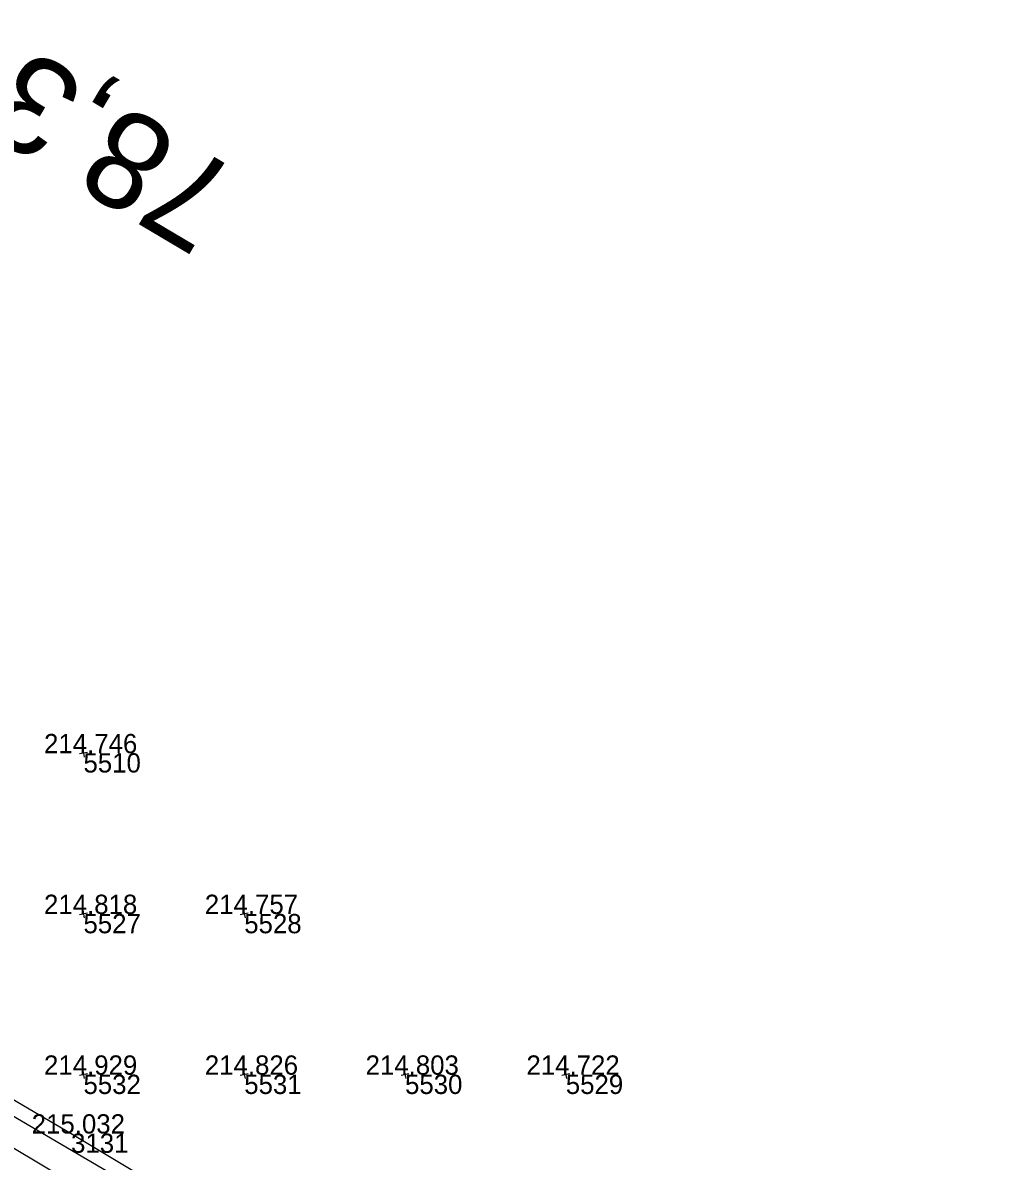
# Model space of a CAD drawing. Extents: x -556590 to -554855, y -1137918 to -1135717.
# Drawn here: x -556203.8 to -556143.5, y -1135955.4 to -1135884.6 of the extents above; entities that cross this region are included whole.
import ezdxf

# ---------------------------------------------------------------- set-up
doc = ezdxf.new("R2010")
doc.units = 0
for name, color, linetype in [('Vrstva 1', 7, 'Continuous'), ('Vrstva 4', 7, 'Continuous'), ('Vrstva 49', 7, 'Continuous'), ('Vrstva 60', 7, 'Continuous'), ('Vrstva 61', 7, 'Continuous'), ('Vrstva 7', 7, 'Continuous')]:
    doc.layers.add(name, color=color, linetype=linetype)

msp = doc.modelspace()

# ---------------------------------------------------------------- linework, layer by layer
at = {"layer": 'Vrstva 1'}
msp.add_lwpolyline([(-556135.067, -1135995.727), (-556144.312, -1135990.237), (-556153.674, -1135984.672), (-556162.941, -1135979.165), (-556173.088, -1135973.143), (-556181.842, -1135967.944), (-556190.254, -1135962.947), (-556199.181, -1135957.655), (-556207.918, -1135952.464), (-556216.868, -1135947.156), (-556226.361, -1135941.515), (-556235.294, -1135936.214), (-556243.937, -1135931.088), (-556256.031, -1135923.92), (-556265.354, -1135918.384), (-556274.631, -1135912.892), (-556283.923, -1135907.384), (-556293.438, -1135901.745), (-556302.474, -1135896.384), (-556311.953, -1135890.765), (-556321.097, -1135885.34)], dxfattribs=at)
at = {"layer": 'Vrstva 4'}
for points in [[(-556149.731, -1135985.089), (-556163.363, -1135976.906), (-556174.301, -1135970.297), (-556174.772, -1135969.888), (-556175.532, -1135969.34), (-556176.326, -1135968.917), (-556176.902, -1135968.731), (-556177.6, -1135968.488), (-556178.321, -1135968.184), (-556179.13, -1135967.714), (-556179.692, -1135967.337), (-556180.432, -1135966.771), (-556181.478, -1135966.107), (-556194.778, -1135958.212), (-556210.442, -1135949.031), (-556226.265, -1135939.722), (-556241.252, -1135930.938), (-556259.28, -1135919.973), (-556269.052, -1135914.244), (-556284.849, -1135904.913), (-556302.391, -1135894.488), (-556319.187, -1135884.553)], [(-556217.465, -1135943.841), (-556200.771, -1135953.661), (-556190.951, -1135959.555)]]:
    msp.add_lwpolyline(points, dxfattribs=at)
at = {"layer": 'Vrstva 49'}
for p, q in [((-556199.754, -1135929.953), (-556200.246, -1135930.047)), ((-556200.047, -1135929.754), (-556199.953, -1135930.246)), ((-556199.754, -1135939.953), (-556200.246, -1135940.047)), ((-556200.047, -1135939.754), (-556199.953, -1135940.246)), ((-556189.754, -1135939.953), (-556190.246, -1135940.047)), ((-556190.047, -1135939.754), (-556189.953, -1135940.246)), ((-556199.754, -1135949.953), (-556200.246, -1135950.047)), ((-556200.047, -1135949.754), (-556199.953, -1135950.246)), ((-556189.754, -1135949.953), (-556190.246, -1135950.047)), ((-556190.047, -1135949.754), (-556189.953, -1135950.246)), ((-556179.754, -1135949.953), (-556180.246, -1135950.047)), ((-556180.047, -1135949.754), (-556179.953, -1135950.246)), ((-556169.754, -1135949.953), (-556170.246, -1135950.047)), ((-556170.047, -1135949.754), (-556169.953, -1135950.246))]:
    msp.add_line(p, q, dxfattribs=at)
at = {"layer": 'Vrstva 60'}
for p, q in [((-556200, -1135930), (-556200, -1135930)), ((-556200, -1135940), (-556200, -1135940)), ((-556190, -1135940), (-556190, -1135940)), ((-556200, -1135950), (-556200, -1135950)), ((-556190, -1135950), (-556190, -1135950)), ((-556180, -1135950), (-556180, -1135950)), ((-556170, -1135950), (-556170, -1135950)), ((-556200.771, -1135953.661), (-556200.771, -1135953.661))]:
    msp.add_line(p, q, dxfattribs=at)

# ---------------------------------------------------------------- texts
for s, p in [('5510', (-556200, -1135931.2)), ('5527', (-556200, -1135941.2)), ('5528', (-556190, -1135941.2)), ('5532', (-556200, -1135951.2)), ('5531', (-556190, -1135951.2)), ('5530', (-556180, -1135951.2)), ('5529', (-556170, -1135951.2)), ('3131', (-556200.771, -1135954.861))]:
    msp.add_text(s, height=1.2, dxfattribs=at).set_placement(p)
at = {"layer": 'Vrstva 61'}
for s, p in [('214.746', (-556202.452, -1135930)), ('214.818', (-556202.454, -1135940)), ('214.757', (-556192.452, -1135940)), ('214.929', (-556202.454, -1135950)), ('214.826', (-556192.452, -1135950)), ('214.803', (-556182.452, -1135950)), ('214.722', (-556172.448, -1135950)), ('215.032', (-556203.219, -1135953.661))]:
    msp.add_text(s, height=1.2, dxfattribs=at).set_placement(p)
at = {"layer": 'Vrstva 7'}
msp.add_text('78,3', height=6, rotation=149.31436, dxfattribs=at).set_placement((-556190, -1135894))

doc.saveas('drawing.dxf')
